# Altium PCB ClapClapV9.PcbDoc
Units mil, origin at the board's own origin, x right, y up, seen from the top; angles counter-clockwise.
Board outline 2204.72 x 469.32 mil, 2 copper layers (Top Layer, Bottom Layer); 20 components, 21 nets, 60 pads, 14 vias.
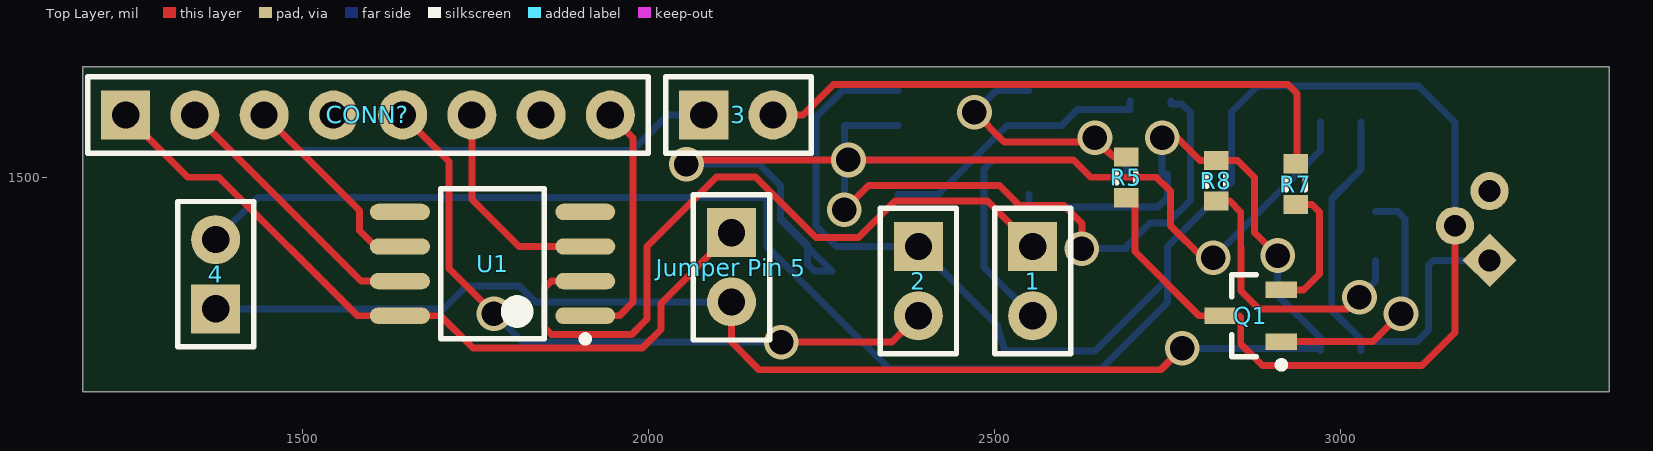
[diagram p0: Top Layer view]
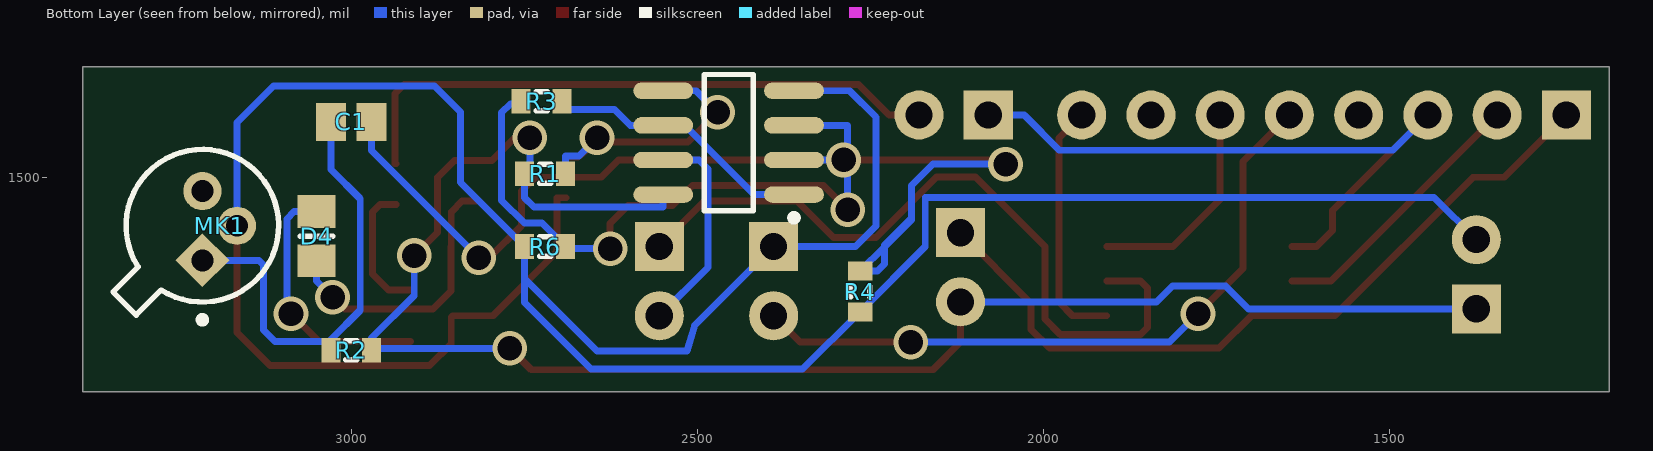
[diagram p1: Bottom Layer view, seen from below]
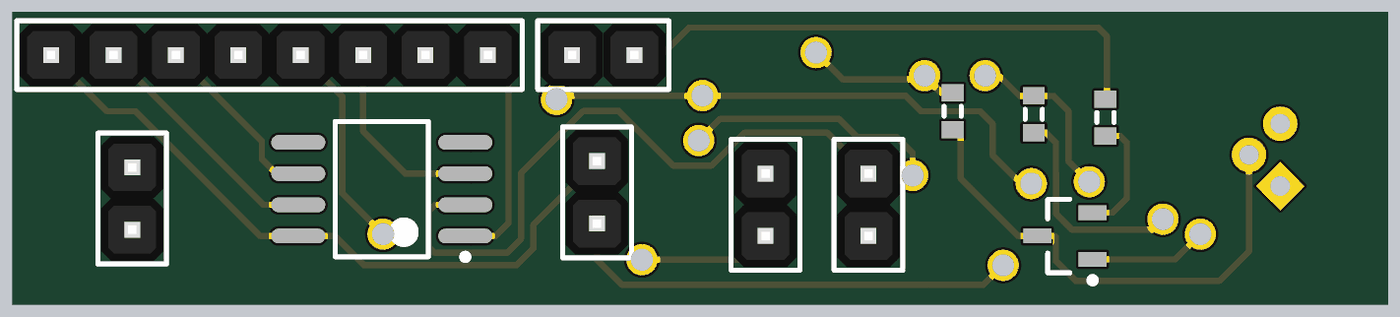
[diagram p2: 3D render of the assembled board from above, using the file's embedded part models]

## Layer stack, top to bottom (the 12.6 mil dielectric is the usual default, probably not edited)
Top Solder: solder mask 0.4, Solder Resist, Dk 3.5
Top Layer: signal copper 1.4
Dielectric 1: dielectric 12.6, FR-4, Dk 4.8
Bottom Layer: signal copper 1.4
Bottom Solder: solder mask 0.4, Solder Resist, Dk 3.5

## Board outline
1183.07,1189.96 3387.8,1189.96 3387.8,1659.28 1183.07,1659.28

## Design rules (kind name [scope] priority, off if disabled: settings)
Clearance [All] p1: gap=10
PolygonConnect [All] p1: connectstyle=Relief reliefconductorwidth=10 reliefentries=4 polygonreliefangle="90 Angle" airgapwidth=10
RoutingVias [All] p1: holewidth=35.43 width=50 viastyle="Through Hole" minholewidth=35.43 minwidth=50 maxholewidth=35.43 maxwidth=50
SolderMaskExpansion [All] p1: expansion=4
UnpouredPolygon [All] p1: allowunpoured=FALSE
Width [All] p1: maxlimit=10 minlimit=10 preferedwidth=10
29 further rules are at their usual default settings.

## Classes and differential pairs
component class ClapClap: 1 2 3 C1 CONN? D4 "Jumper Pin 5" MK1 Q1 R1 R2 R3 R4 R5 R6 R7 R8

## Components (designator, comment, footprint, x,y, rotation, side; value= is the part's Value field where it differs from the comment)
1 "Jumper Signal Input" "1x2x2.54 Pin Header TH V" 2555,1350 r270 top
2 "Jumper GND" "1x2x2.54 Pin Header TH V" 2390,1350 r270 top
3 "Jumper Signal Output" "1x2x2.54 Pin Header TH V" 2130,1590 r0 top
4 "Power" "1x2x2.54 Pin Header TH V" 1375,1360 r90 top
C1 "Cap Pol3" C0805 3000,1580 r180 bottom
CONN? "Header Array" "1x8x2.54 Pin Header TH V" 1595,1590 r0 top
D4 "ED3" 6-0805_N 3050,1415 r90 bottom
"Jumper Pin 5" "Connector" "1x2x2.54 Pin Header TH V" 2120,1370 r270 top
MK1 "Microphone" TO-52 3215,1430 r90 bottom
Q1 "QNPN" SOT-23B_N 2870,1300 r180 top
R1 "Res3" J1-0603 2720,1505 r0 bottom
R2 "Res3" J1-0603 3000,1250 r180 bottom
R3 "Res3" J1-0603 2725,1610 r180 bottom
R4 "Res3" J1-0603 2265,1335 r90 bottom
R5 "Res3" J1-0603 2690,1500 r270 top
R6 "Res3" J1-0603 2720,1400 r0 bottom
R7 "Res3" J1-0603 2935,1490 r270 top
R8 "Res3" J1-0603 2820,1495 r90 top
U1 "ATtiny45V-10SU" 8S2_N 1775,1375 r180 top
? "MCP6002T-E/SN" SOIC-SN8_N 2455,1550 r0 bottom

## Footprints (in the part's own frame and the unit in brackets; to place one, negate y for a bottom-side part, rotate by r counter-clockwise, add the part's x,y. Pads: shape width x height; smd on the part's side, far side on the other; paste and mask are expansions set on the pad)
"1x2x2.54 Pin Header TH V" [mm] "1x2x2.54 Pin Header TH V"
  rect 1.8x1.8 hole 1: 1(-1.27,0)
  round 1.8 hole 1: 2(1.27,0)
  silkscreen extent -2.67,-1.4 2.67,1.4, body extent -2.54,-1.27 2.54,1.27, height 8.55
"1x8x2.54 Pin Header TH V" [mm] "1x8x2.54 Pin Header TH V"
  rect 1.8x1.8 hole 1: 1(-8.89,0)
  round 1.8 hole 1: 2(-6.35,0) 3(-3.81,0) 4(-1.27,0) 5(1.27,0) 6(3.81,0) 7(6.35,0) 8(8.89,0)
  silkscreen extent -10.29,-1.4 10.29,1.4, body extent -10.16,-1.27 10.16,1.27, height 8.55
6-0805_N [mm] "Chip Resistor, Body 2.0x1.2mm, IPC Medium Density"
  rect 1.2x1.4 smd: 1(-0.9,0) 2(0.9,0)
  silkscreen extent 0,-0.6 0,0.6, body extent -1.07,-0.7 1.07,0.7, height 0.7
8S2_N [mm] "SOP, 8-Leads, Body 5.3x5.3mm, Pitch 1.27mm, IPC Medium Density"
  oval 2.2x0.6 smd: 1(-3.4,1.905) 2(-3.4,0.635) 3(-3.4,-0.635) 4(-3.4,-1.905) 5(3.4,-1.905) 6(3.4,-0.635) 7(3.4,0.635) 8(3.4,1.905)
  silkscreen extent -3.52,-2.75 1.9,2.88, body extent -2.73,-2.75 2.73,2.75, height 2.16
C0805 [mm] "Chip Capacitor, Body 2.0x1.3mm, IPC High Density"
  rect 1.1x1.4 smd: 1(-0.75,0) 2(0.75,0)
  body extent -1.1,-0.72 1.1,0.72, height 1.4
J1-0603 [mm] "Chip Resistor, Body 1.6x0.8mm, IPC High Density"
  rect 0.7x0.9 smd: 1(-0.75,0) 2(0.75,0)
  silkscreen extent -0.2,-0.35 0.2,0.35, body extent -0.85,-0.48 0.85,0.48, height 0.9
SOIC-SN8_N [mm] "SOIC, 8-Leads, Body 4.9x3.8mm, Pitch 1.27mm, IPC Medium Density"
  oval 2.2x0.6 smd: 1(-2.4,1.905) 2(-2.4,0.635) 3(-2.4,-0.635) 4(-2.4,-1.905) 5(2.4,-1.905) 6(2.4,-0.635) 7(2.4,0.635) 8(2.4,1.905)
  silkscreen extent -2.52,-2.5 0.9,2.88, body extent -2,-2.5 2,2.5, height 1.75
SOT-23B_N [mm] "SOT23, 3-Leads, Body 2.9x1.3mm, Pitch 0.95mm, Lead Span 2.4mm, IPC Medium Density"
  rect 1.15x0.6 smd: 1(-1.125,0.95) 2(-1.125,-0.95) 3(1.125,0)
  silkscreen extent -1.25,-1.5 0.7,1.92, body extent -0.7,-1.5 0.7,1.5, height 1.14
TO-52 [mm] "Can; 3 Leads; Pin Circle Dia. 2.54 mm; Lead Dia. 0.48 mm (max)"
  rect 1.4x1.4 hole 0.8 rot 45: 1(-1.27,0)
  round 1.4 hole 0.8: 2(0,-1.27) 3(1.27,0)
  silkscreen extent -3.57,-2.8 2.8,3.28, body extent -2.81,-2.81 2.81,2.81, height 2.67

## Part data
1 2 3 4 "Jumper Pin 5": library part "Header 1x2"
C1: "Polarized Capacitor (Surface Mount)"
CONN?: library part "Header 1x8"
D4: library part LED3, "Typical BLUE SiC LED"
MK1: library part Mic1
Q1: "NPN Bipolar Transistor"
R1 R2 R3 R4 R5 R6 R7 R8: "Resistor"
U1: "Low Power tinyAVR® 8-Bit Microcontroller, 4K Flash Memory, 10MHz, Industrial Temperature, 8-Lead SOIC, Pb-Free"
?: "1 MHz, Low-Power Operational Amplifier, 8-Pin SOIC, Extended Temperature, Tape and Reel"

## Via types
v1: diameter 50, hole 35.43, Top Layer to Bottom Layer, 14 vias

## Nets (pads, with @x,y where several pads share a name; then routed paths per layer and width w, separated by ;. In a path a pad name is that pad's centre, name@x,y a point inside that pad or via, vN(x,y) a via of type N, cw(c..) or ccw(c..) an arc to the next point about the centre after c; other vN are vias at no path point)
3V: 4.1 "Jumper Pin 5.2" ?.8 R1.2 R2.2 R8.2 | length 2470.3
  Top Layer w10: 2120,1320 2120,1262 2160,1222 2740,1222 v1(2771,1253) ; v1(2742,1557) 2764.53,1557 2797,1524.53 R8.2 2851.01,1524.53 2875.53,1500 2875.53,1420.47 v1(2909,1387)
  Bottom Layer w10: 4.1 1703.9,1310 1737,1343.1 1814,1343.1 1837.1,1320 2120,1320 ; ?.8 2549.49,1457 2736.09,1457 2749.53,1470.43 R1.2 2742,1505 v1(2742,1557) ; v1(2771,1253) R2.2@2970.47,1253 ; v1(2909,1387) 2909,1329.42 2970.47,1267.94 R2.2@2970.47,1253 ; R2.2 R2.2@2970.47,1253
GND: 2.1 4.2 ?.4 MK1.2 Q1.3 R4.1 R5.2 R6.2 | length 4153.7
  Top Layer w10: R5.2 2702.72,1470.47 2702.72,1392.81 2795.53,1300 Q1.3 2853,1300 2855.54,1297.46 2855.54,1259.46 2887,1228 3117.17,1228 3165,1275.83 MK1.2
  Bottom Layer w10: 4.2 1436,1471 2171,1471 2171,1400 R4.1@2265.26,1305.74 ; R4.1 R4.1@2265.26,1305.74 ; ?.4 2280.25,1625 2242,1586.75 2242,1429.78 2271.78,1400 2.1 2504,1286 2515,1249 2645,1249 2749.53,1353.53 ; MK1.2 3165,1579 3112,1632 2880,1632 2842.31,1594.31 2842.31,1492.78 R6.2 2749.53,1353.53 ; R4.1@2265.26,1305.74 2348,1223 2653.53,1223 2749.53,1319 2749.53,1353.53
Net1_1: 1.1 U1.2 | length 1069.6
  Top Layer w10: U1.2 1860,1350 1850,1340 1850,1283.19 1860,1273.19 1976,1273.19 1998,1295.19 1998,1400 2098.34,1500.34 2154.71,1500.34 2242.2,1412.85 2303.66,1412.85 2356.31,1465.5 2489.5,1465.5 1.1
Net2_2: 2.2 CONN?.5 | length 987.4
  Top Layer w10: CONN?.5 1712,1523 1712,1368 v1(1777,1303) ; v1(2192,1262) 2352,1262 2.2
  Bottom Layer w10: v1(1777,1303) 1818,1262 v1(2192,1262)
Net3_1: 3.1 CONN?.3 U1.6 | length 969.2
  Top Layer w10: CONN?.3 1582.83,1452.17 1582.83,1423 1605.83,1400 U1.6
  Bottom Layer w10: CONN?.3 1496,1539 1977,1539 2028,1590 3.1
Net3_2: 3.2 R7.1 | length 884.1
  Top Layer w10: 3.2 2223,1590 2267.2,1634.2 2923.48,1634.2 2937,1620.68 2937,1519.53 R7.1
Net_1: ?.1 ?.6 R3.2 | length 397.9
  Bottom Layer w10: ?.1 2418,1475 2518,1575 ?.6 2597,1575 2620,1598 2695.47,1598 R3.2
Net_2: ?.2 C1.2 R4.2 | length 1607.4
  Top Layer w10: v1(2055,1519) 2061,1525 v1(2289,1525) 2614,1525 2639,1500 2734,1500 2754,1480 2754,1430 2800,1384 v1(2816,1384)
  Bottom Layer w10: v1(2055,1519) 2160,1519 2191,1488 2191,1441 ; v1(2289,1525) ?.2 ; v1(2816,1384) 2970.47,1538.47 C1.2 ; 2191,1441 2230,1402 2230,1399.53 ; 2191,1441 2191,1438.53 2230,1399.53 ; 2230,1399.53 R4.2 2240,1364.53 2230,1374.53 2230,1399.53
Net_3: ?.3 R3.1 R6.1 | length 967.2
  Top Layer w10: v1(2283,1453) 2318,1488 2507,1488 2536,1459 2600,1459 2626,1433 v1(2626,1397)
  Bottom Layer w10: v1(2283,1453) 2283,1575 ?.3 ; v1(2626,1397) 2690.47,1397 R6.1 2724.47,1434 2750,1434 2782.72,1466.72 2782.72,1593.28 2770,1606 2754.53,1606 R3.1
Net_5: ?.5 R1.1 R5.1 | length 587.7
  Top Layer w10: v1(2471,1594) 2513.96,1551.04 ; v1(2645,1557) R5.1@2672.47,1529.53 ; R5.1 R5.1@2672.47,1529.53 ; 2513.96,1551.04 v1@2645,1551.04 ; 2513.96,1551.04 v1@2645,1551.04 ; v1@2645,1551.04 R5.1@2672.47,1529.53
  Bottom Layer w10: v1(2471,1594) 2502,1625 ?.5 ; v1(2645,1557) 2671,1531 2690.47,1531 R1.1
Net_7: 1.2 ?.7 | length 310.9
  Bottom Layer w10: ?.7 2498,1525 2485,1512 2485,1370 1.2
NetC1_1: C1.1 MK1.1 R2.1 | length 654.2
  Bottom Layer w10: R2.1 R2.1@3029.53,1262.72 ; C1.1 3029.53,1511.53 2987,1469 2987,1307.94 3029.53,1265.42 R2.1@3029.53,1262.72 ; MK1.1 3133.53,1380 3127,1373.47 3127,1279.72 3110,1262.72 R2.1@3029.53,1262.72
NetCONN?_1: "Jumper Pin 5.1" CONN?.1 U1.8 | length 1105.9
  Top Layer w10: CONN?.1 1335,1500 1380,1500 1580,1300 U1.8 1699.84,1300 1746.65,1253.19 1991.19,1253.19 2018,1280 2018,1318 2120,1420
NetCONN?_2: CONN?.2 U1.7 | length 395.6
  Top Layer w10: CONN?.2 1585,1350 U1.7
NetCONN?_6: CONN?.6 U1.3 | length 314
  Top Layer w10: CONN?.6 1745,1468 1813,1400 U1.3
NetCONN?_7: CONN?.7
NetCONN?_8: CONN?.8 U1.1 | length 361.1
  Top Layer w10: U1.1 1958,1300 1978,1320 1978,1557 CONN?.8
NetD4_1: D4.1 R8.1 | length 407
  Top Layer w10: R8.1 2840.06,1465.47 2855.53,1450 2855.53,1400.47 2856,1400 2856,1336 2882,1310 3010,1310 v1(3027,1327)
  Bottom Layer w10: v1(3027,1327) 3050,1350 D4.1
NetD4_2: D4.2 Q1.1 | length 376.3
  Top Layer w10: Q1.1 3046.6,1262.6 v1(3087,1303)
  Bottom Layer w10: D4.2 3082.57,1450.43 3093,1440 3093,1309 v1(3087,1303)
NetQ1_2: Q1.2 R7.2 | length 192.4
  Top Layer w10: Q1.2 2946.4,1337.4 2969,1360 2969,1450 2958.53,1460.47 R7.2
NetU1_5: U1.5
pads on no net: CONN?.4 MK1.3 U1.4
